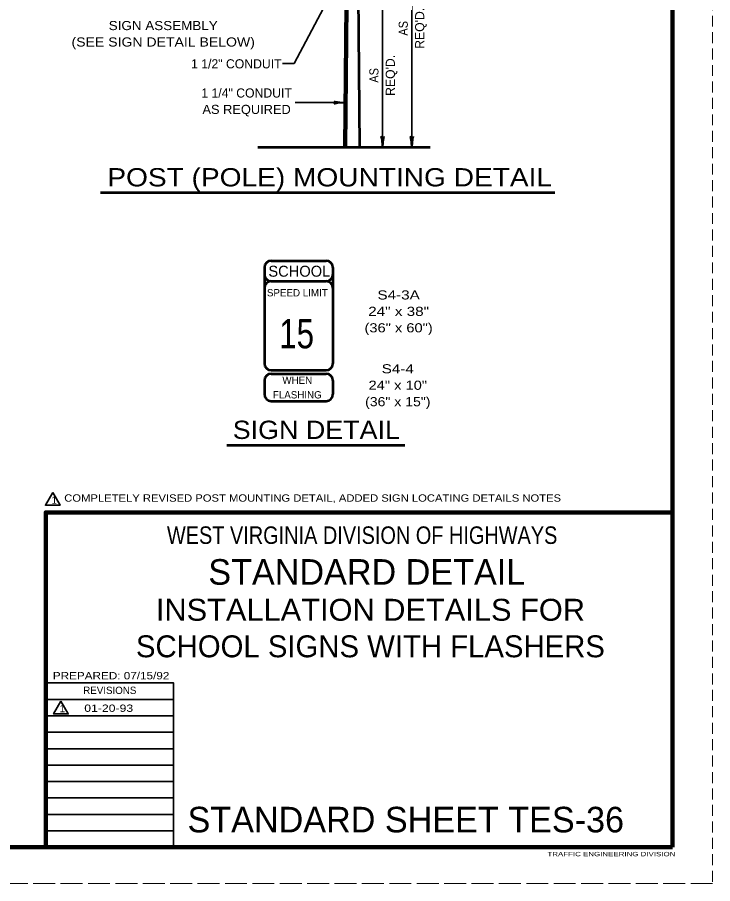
# Model space of a CAD drawing. Extents: x -1 to 679, y 1 to 441.
# Drawn here: x 488.5 to 678.8, y 0.8 to 237.8 of the extents above; entities that cross this region are included whole.
import ezdxf
from ezdxf.enums import TextEntityAlignment as Align

# ---------------------------------------------------------------- set-up
doc = ezdxf.new("R2010")
doc.units = 0
doc.linetypes.add('LONG_DASHED', pattern=[7.5, 6, -1.5])
doc.linetypes.add('MEDIUM_DASHED', pattern=[4.5, 3, -1.5])
doc.layers.add('1', color=7, linetype='Continuous', lineweight=35)
doc.layers.add('61', color=7, linetype='Continuous', lineweight=35)

msp = doc.modelspace()

# ---------------------------------------------------------------- linework, layer by layer
at = {"layer": '1', "linetype": 'MEDIUM_DASHED', "lineweight": 13}
msp.add_line((678.842, 440.796), (678.822, 0.776), dxfattribs=at)
at = {"layer": '1', "lineweight": 53}
for p, q in [((581.334, 288.812), (582.135, 202.343)), ((578.274, 241.357), (577.913, 202.347)), ((554.274, 202.354), (601.457, 202.354)), ((511.252, 189.911), (635.615, 189.911)), ((557.979, 171.246), (572.979, 171.246)), ((556.104, 169.371), (556.104, 143.121)), ((574.854, 169.371), (574.854, 143.121)), ((557.979, 165.621), (572.979, 165.621)), ((557.979, 141.246), (572.979, 141.246)), ((557.979, 140.308), (572.979, 140.308)), ((556.104, 138.433), (556.104, 134.683)), ((574.854, 138.433), (574.854, 134.683)), ((557.979, 132.808), (572.979, 132.808)), ((545.854, 120.799), (594.524, 120.799))]:
    msp.add_line(p, q, dxfattribs=at)
at = {"layer": '1'}
for p, q in [((596.457, 275.571), (596.457, 202.354)), ((588.457, 242.825), (588.457, 202.354)), ((564.558, 214.506), (578.025, 214.506)), ((531.222, 51.196), (496.242, 51.196)), ((531.222, 46.696), (496.242, 46.696)), ((531.222, 42.196), (496.242, 42.196)), ((531.222, 37.676), (496.242, 37.676)), ((531.222, 33.196), (496.242, 33.196)), ((531.222, 28.716), (496.242, 28.716)), ((531.222, 24.216), (496.242, 24.216)), ((531.222, 19.716), (496.242, 19.716)), ((531.222, 15.196), (496.242, 15.196))]:
    msp.add_line(p, q, dxfattribs=at)
at = {"layer": '1', "lineweight": 53}
msp.add_lwpolyline([(579.105, 277.093), (579.077, 274.093), (578.802, 244.352), (578.774, 241.352), (578.413, 202.343)], dxfattribs=at)
at = {"layer": '1'}
for points in [[(573.112, 241.95), (564.215, 225.174), (561.022, 225.174)], [(531.222, 10.716), (531.222, 55.676), (496.242, 55.676)]]:
    msp.add_lwpolyline(points, dxfattribs=at)
for points in [[(498.159, 107.765), (496.159, 104.301), (500.159, 104.301)], [(500.401, 50.697), (498.401, 47.233), (502.401, 47.233)]]:
    msp.add_lwpolyline(points, close=True, dxfattribs=at)
at = {"layer": '1', "lineweight": 158}
msp.add_lwpolyline([(496.222, 10.756), (496.222, 102.336), (667.882, 102.336)], dxfattribs=at)
at = {"layer": '1', "lineweight": 53}
for centre, start, end in [((557.979, 169.371), 90, 180), ((572.979, 169.371), 0, 90), ((557.979, 167.496), 180, 270), ((572.979, 167.496), 270, 0), ((557.979, 163.746), 90, 180), ((572.979, 163.746), 0, 90), ((557.979, 143.121), 180, 270), ((572.979, 143.121), 270, 0), ((557.979, 138.433), 90, 180), ((572.979, 138.433), 0, 90), ((557.979, 134.683), 180, 270), ((572.979, 134.683), 270, 0)]:
    msp.add_arc(centre, 1.875, start, end, dxfattribs=at)
at = {"layer": '1', "lineweight": 40}
for centre, major_axis, ratio, start_param, end_param in [((576.934, 214.23), (1.786, 0.156), 0.122415, 0.8963533, 3.1415927), ((576.934, 214.23), (1.786, 0.156), 0.122415, 0.8963533, 3.1415927), ((576.905, 214.718), (1.756, -0.176), 0.07063, 3.1407148, 5.41811), ((576.905, 214.718), (1.756, -0.176), 0.07063, 3.1407148, 5.41811), ((588.181, 203.445), (0.156, -1.786), 0.122415, 0.8963533, 3.1415927), ((588.181, 203.445), (0.156, -1.786), 0.122415, 0.8963533, 3.1415927), ((588.669, 203.475), (-0.176, -1.756), 0.07063, 3.1407148, 5.41811), ((588.669, 203.475), (-0.176, -1.756), 0.07063, 3.1407148, 5.41811), ((596.181, 203.445), (0.156, -1.786), 0.122415, 0.8963533, 3.1415927), ((596.181, 203.445), (0.156, -1.786), 0.122415, 0.8963533, 3.1415927), ((596.669, 203.475), (-0.176, -1.756), 0.07063, 3.1407148, 5.41811), ((596.669, 203.475), (-0.176, -1.756), 0.07063, 3.1407148, 5.41811)]:
    msp.add_ellipse(centre, major_axis=major_axis, ratio=ratio, start_param=start_param, end_param=end_param, dxfattribs=at)
at = {"layer": '61', "lineweight": 158}
for p, q in [((667.862, 430.796), (667.882, 10.756)), ((667.882, 10.756), (28.822, 10.776))]:
    msp.add_line(p, q, dxfattribs=at)
at = {"layer": '61', "linetype": 'LONG_DASHED', "lineweight": 13}
msp.add_line((678.822, 0.776), (-1.238, 0.756), dxfattribs=at)

# ---------------------------------------------------------------- texts
at = {"layer": '1'}
for p in [(599.865, 234.844), (591.836, 221.957)]:
    msp.add_text("REQ'D.", height=2.5, rotation=90, dxfattribs=at).set_placement(p, align=Align.CENTER)
for s, height, width, p in [('SIGN ASSEMBLY', 2.5, 1.1, (528.402, 234.348)), ('(SEE SIGN DETAIL BELOW)', 2.5, 1.15, (528.402, 229.848)), ('AS REQUIRED', 2.5, 1.05, (551.232, 211.396)), ('S4-3A', 2.5, 1.25, (592.854, 160.63)), ('24" x 38"', 2.5, 1.25, (592.854, 156.13)), ('(36" x 60")', 2.5, 1.2, (592.854, 151.63)), ('S4-4', 2.5, 1.25, (592.63, 140.416)), ('24" x 10"', 2.5, 1.2, (592.63, 135.916)), ('(36" x 15")', 2.5, 1.15, (592.63, 131.416)), ('WEST VIRGINIA DIVISION OF HIGHWAYS', 4.795, 0.85, (582.871, 93.736)), ('INSTALLATION DETAILS FOR', 6, 1.05, (585.135, 72.713))]:
    msp.add_text(s, height=height, dxfattribs=dict(at, width=width)).set_placement(p, align=Align.CENTER)
at = {"layer": '1', "width": 0.9}
for p in [(595.365, 234.844), (587.336, 221.958)]:
    msp.add_text('AS', height=2.5, rotation=90, dxfattribs=at).set_placement(p, align=Align.CENTER)
at = {"layer": '1'}
for s, height, p in [('1 1/2" CONDUIT', 2.5, (536.034, 223.876)), ('SCHOOL', 3, (557.194, 166.866)), ('SPEED LIMIT', 2, (556.801, 161.476)), ('1', 2, (497.823, 104.738)), ('REVISIONS', 1.998, (506.502, 52.676)), ('1', 2, (500.065, 47.67)), ('STANDARD SHEET TES-36', 6.993, (535.062, 14.796))]:
    msp.add_text(s, height=height, dxfattribs=at).set_placement(p)
for s, height, p in [('1 1/4" CONDUIT', 2.5, (551.232, 215.896)), ('WHEN', 2, (565.109, 137.546)), ('FLASHING', 2, (565.109, 133.546)), ('STANDARD DETAIL', 6.993, (584.139, 82.576)), ('SCHOOL SIGNS WITH FLASHERS', 6, (585.135, 62.713))]:
    msp.add_text(s, height=height, dxfattribs=at).set_placement(p, align=Align.CENTER)
for s, height, width, p in [('POST (POLE) MOUNTING DETAIL', 5, 1.15, (513.101, 191.575)), ('15', 8, 0.8, (560.169, 147.27)), ('SIGN DETAIL', 5, 1.1, (547.439, 122.463)), ('COMPLETELY REVISED POST MOUNTING DETAIL, ADDED SIGN LOCATING DETAILS NOTES', 2, 1.15, (501.298, 105.298)), ('PREPARED: 07/15/92', 1.998, 1.2, (498.182, 56.676)), ('01-20-93', 2, 1.25, (506.79, 47.782)), ('TRAFFIC ENGINEERING DIVISION', 1.2, 1.35, (633.602, 8.256))]:
    msp.add_text(s, height=height, dxfattribs=dict(at, width=width)).set_placement(p)

doc.saveas('drawing.dxf')
